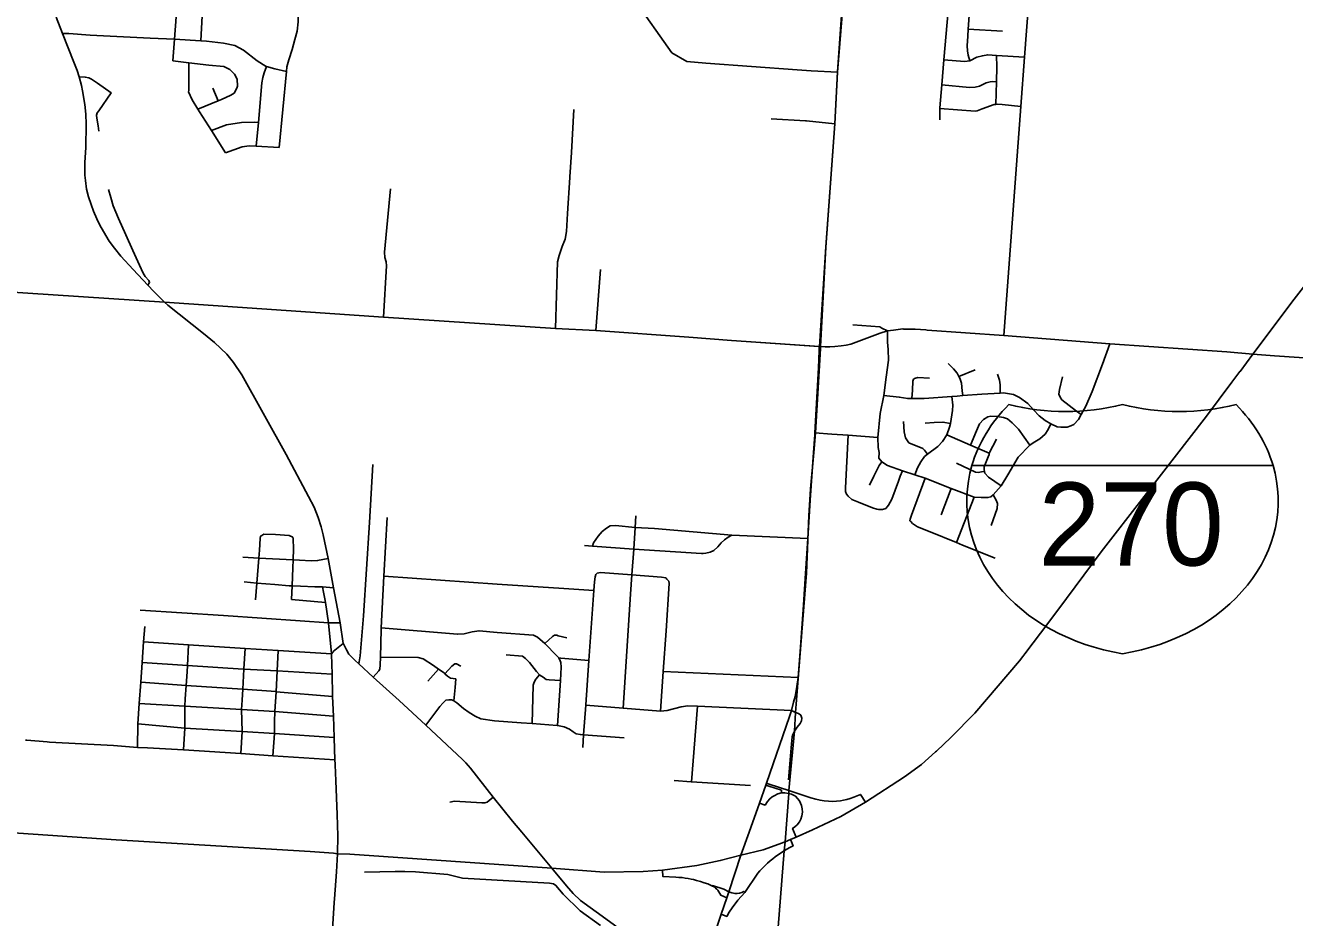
# Model space of a CAD drawing. Extents: x 1755200 to 1902939, y 644115 to 788070.
# Drawn here: x 1838211 to 1853497, y 681325 to 692073 of the extents above; entities that cross this region are included whole.
import ezdxf

# ---------------------------------------------------------------- set-up
doc = ezdxf.new("R2010")
doc.units = 0
for name, color, linetype in [('GM_X_City_Street', 7, 'Continuous'), ('GM_X_County_Road', 7, 'Continuous'), ('GM_X_Interchange_Ramps', 7, 'Continuous'), ('GM_X_Interstate_Route', 7, 'Continuous'), ('GM_X_Interstate_Shield', 7, 'Continuous'), ('GM_X_Township', 7, 'Continuous')]:
    doc.layers.add(name, color=color, linetype=linetype)

msp = doc.modelspace()

# ---------------------------------------------------------------- linework, layer by layer
at = {"layer": 'GM_X_City_Street'}
for points in [[(1840323, 691887), (1840356, 692494), (1840372, 692805), (1840373, 692814), (1840380, 692899), (1840402, 692971), (1840455, 693057), (1840481, 693100), (1840756, 693487), (1840776, 693552), (1840782, 693644), (1840793, 693749), (1840828, 694069)], [(1847676, 691527), (1847506, 691537), (1846406, 691618), (1846179, 691637), (1845998, 691744), (1845543, 692389), (1845432, 692563), (1845396, 692630), (1845365, 692816), (1845353, 692917), (1845358, 693015), (1845396, 693399), (1845412, 693692), (1845413, 693751)], [(1849993, 688339), (1850200, 691096), (1850245, 691692), (1850400, 693755)], [(1839985, 691645), (1840007, 691907), (1840026, 692176), (1840039, 692497), (1840044, 692575)], [(1849223, 690935), (1849225, 691071), (1849225, 691081), (1849248, 691356), (1849274, 691657), (1849314, 692113), (1849332, 692325)], [(1849585, 691648), (1849565, 691716), (1849559, 691766), (1849553, 691827), (1849560, 691943), (1849567, 692026), (1849587, 692305)], [(1838580, 692171), (1838658, 691975), (1838795, 691631), (1838833, 691530), (1838859, 691453), (1838885, 691349), (1838900, 691285), (1838928, 691120), (1838940, 691004), (1838945, 690884), (1838939, 690604), (1838929, 690423), (1838927, 690333), (1838929, 690271), (1838934, 690206), (1838949, 690101), (1838973, 690010), (1839002, 689916), (1839031, 689837), (1839071, 689745), (1839107, 689667), (1839152, 689589), (1839221, 689475), (1839283, 689389), (1839361, 689295), (1839511, 689131), (1839687, 688943), (1839759, 688869), (1839886, 688739)], [(1841491, 692249), (1841497, 692207), (1841495, 692116), (1841486, 692002), (1841458, 691904), (1841423, 691784), (1841383, 691659), (1841361, 691573), (1841354, 691516), (1841267, 690603)], [(1847992, 691508), (1848048, 692200)], [(1849567, 692026), (1849979, 692005)], [(1838658, 691975), (1838736, 691975), (1838991, 691954), (1839714, 691918), (1840007, 691907)], [(1840007, 691907), (1840323, 691887), (1840391, 691883), (1840598, 691859), (1840734, 691830), (1840838, 691776), (1841003, 691646), (1841109, 691580), (1841115, 691579), (1841215, 691549), (1841354, 691516)], [(1849274, 691657), (1849523, 691640), (1849585, 691648), (1849668, 691691), (1849736, 691707), (1849802, 691719), (1849906, 691711), (1850245, 691692)], [(1849900, 691122), (1849905, 691395), (1849909, 691573), (1849906, 691711)], [(1839985, 691645), (1840180, 691622), (1840421, 691595), (1840603, 691578), (1840674, 691543), (1840731, 691486), (1840761, 691427), (1840765, 691343), (1840757, 691319)], [(1840180, 691622), (1840178, 691287), (1840176, 691271), (1840220, 691175), (1840289, 691065), (1840310, 691031), (1840451, 690808), (1840622, 690537)], [(1840991, 690618), (1841017, 690902), (1841060, 691381), (1841071, 691447), (1841088, 691501), (1841115, 691579)], [(1847992, 691508), (1847676, 691527)], [(1839095, 690800), (1839088, 690862), (1839073, 690954), (1839068, 690993), (1839076, 691018), (1839094, 691044), (1839244, 691262), (1839080, 691376), (1839006, 691427), (1838976, 691443), (1838933, 691451), (1838859, 691453)], [(1847773, 688206), (1847853, 689404), (1847959, 690888), (1847992, 691508)], [(1849248, 691356), (1849581, 691327), (1849651, 691331), (1849703, 691342), (1849783, 691380), (1849831, 691394), (1849855, 691398), (1849905, 691395)], [(1840289, 691065), (1840533, 691163), (1840573, 691179), (1840686, 691232), (1840724, 691257), (1840757, 691319)], [(1840533, 691163), (1840469, 691317)], [(1844769, 690248), (1844787, 690541), (1844815, 691061)], [(1849225, 691071), (1849650, 691041), (1849672, 691043), (1849732, 691067), (1849878, 691120), (1849900, 691122), (1849914, 691124), (1849974, 691120), (1850200, 691096), (1850206, 691095)], [(1840451, 690808), (1840634, 690874), (1840815, 690903), (1840971, 690909), (1841017, 690902)], [(1847192, 690947), (1847607, 690924), (1847619, 690923)], [(1847619, 690923), (1847959, 690888)], [(1840622, 690537), (1840823, 690610), (1840907, 690623), (1840991, 690618), (1841267, 690603)], [(1844595, 688421), (1844621, 689227), (1844639, 689303), (1844675, 689410), (1844710, 689500), (1844726, 689592), (1844741, 689807), (1844768, 690240), (1844769, 690248)], [(1839687, 688943), (1839707, 688976), (1839698, 689000), (1839654, 689049), (1839630, 689087), (1839586, 689184), (1839505, 689360), (1839421, 689550), (1839333, 689748), (1839270, 689899), (1839241, 689999), (1839214, 690098)], [(1842524, 688560), (1842562, 689176), (1842558, 689226), (1842539, 689278), (1842537, 689343), (1842607, 690105)], [(1845081, 688396), (1845138, 689133)], [(1836126, 688986), (1837200, 688915), (1839886, 688739), (1842524, 688560), (1844595, 688421), (1845081, 688396), (1846201, 688317), (1846717, 688279), (1847773, 688206)], [(1839886, 688739), (1839927, 688705)], [(1839927, 688705), (1840355, 688360), (1840489, 688253), (1840637, 688114), (1840717, 688014), (1840817, 687862), (1841350, 686903), (1841620, 686399), (1841690, 686271), (1841738, 686144), (1841773, 686033), (1841797, 685935), (1841856, 685650), (1841922, 685300), (1842001, 684875), (1842039, 684627), (1842045, 684615)], [(1848175, 688467), (1848503, 688444), (1848525, 688426), (1848595, 688393)], [(1847773, 688206), (1847845, 688202), (1847900, 688202), (1847961, 688205), (1848034, 688212), (1848094, 688222), (1848151, 688233), (1848507, 688364), (1848593, 688392)], [(1848495, 686930), (1848481, 686990), (1848479, 687109), (1848505, 687397), (1848549, 687615), (1848579, 687836), (1848605, 688041), (1848602, 688171), (1848594, 688259), (1848595, 688393)], [(1848804, 688416), (1848895, 688414), (1848911, 688413)], [(1847771, 688152), (1847772, 688192), (1847773, 688206)], [(1850757, 687232), (1850803, 687248), (1850839, 687266), (1850893, 687326), (1850925, 687385), (1850981, 687485), (1851060, 687664), (1851182, 687991), (1851271, 688239)], [(1847717, 687141), (1847719, 687167), (1847762, 687948), (1847771, 688152)], [(1853256, 688094), (1854025, 688040), (1855415, 687939), (1856313, 687875), (1856498, 687863), (1856659, 687849)], [(1849500, 687613), (1849494, 687671), (1849484, 687763), (1849464, 687825), (1849453, 687845), (1849431, 687883), (1849389, 687937), (1849323, 688001)], [(1849453, 687845), (1849648, 687924)], [(1849952, 687644), (1849951, 687742), (1849941, 687801), (1849919, 687871)], [(1848885, 687579), (1848893, 687679), (1848900, 687789), (1848908, 687811), (1848920, 687819), (1848960, 687833), (1849101, 687822)], [(1850925, 687385), (1850871, 687425), (1850694, 687564), (1850674, 687596), (1850659, 687630), (1850667, 687687), (1850701, 687841)], [(1848549, 687615), (1848736, 687596), (1848837, 687578), (1848885, 687579), (1849035, 687579), (1849370, 687604), (1849434, 687608), (1849500, 687613), (1849731, 687631), (1849952, 687644), (1849992, 687646), (1850110, 687627), (1850184, 687591), (1850285, 687517), (1850353, 687443), (1850422, 687371), (1850492, 687315), (1850562, 687273), (1850639, 687239), (1850682, 687235), (1850757, 687232)], [(1848921, 686661), (1848954, 686742), (1848994, 686817), (1849038, 686879), (1849077, 686909), (1849200, 687002), (1849258, 687060), (1849309, 687140), (1849341, 687235), (1849352, 687277), (1849377, 687436), (1849379, 687500), (1849370, 687604)], [(1848786, 687303), (1848796, 687179), (1848812, 687107), (1848851, 687045), (1848917, 687015), (1848991, 686989), (1849021, 686977), (1849040, 686955), (1849077, 686909)], [(1849046, 687282), (1849157, 687289), (1849261, 687295), (1849352, 687277)], [(1849593, 687018), (1849664, 687190), (1849702, 687274), (1849748, 687327), (1849802, 687357), (1849840, 687365), (1849916, 687363), (1849991, 687349), (1850039, 687332), (1850095, 687284), (1850172, 687210), (1850308, 687016)], [(1849785, 686388), (1849803, 686386), (1849838, 686394), (1849868, 686417), (1849964, 686525), (1850043, 686660), (1850167, 686871), (1850308, 687016), (1850349, 687044), (1850427, 687094), (1850493, 687150), (1850529, 687205), (1850562, 687273)], [(1847414, 683750), (1847438, 683821), (1847463, 683922), (1847481, 683991), (1847493, 684058), (1847506, 684137), (1847517, 684220), (1847545, 684584), (1847583, 685092), (1847605, 685472), (1847634, 685893), (1847662, 686354), (1847702, 686929), (1847717, 687141)], [(1847719, 687167), (1847924, 687150), (1848120, 687136), (1848479, 687109)], [(1848120, 687136), (1848089, 686503), (1848089, 686459), (1848101, 686425), (1848119, 686401), (1848163, 686361), (1848244, 686329), (1848412, 686263), (1848466, 686247), (1848486, 686243)], [(1849309, 687140), (1849593, 687018), (1849792, 686934), (1849820, 686920), (1849818, 686904), (1849806, 686875), (1849758, 686757), (1849756, 686721), (1849761, 686699), (1849766, 686679), (1849811, 686633), (1849964, 686525)], [(1849820, 686920), (1849905, 687088)], [(1842225, 684382), (1842243, 684478), (1842285, 684961), (1842356, 686084), (1842395, 686784)], [(1848375, 686534), (1848429, 686644), (1848495, 686773), (1848527, 686815)], [(1848495, 686930), (1848488, 686861), (1848527, 686815), (1848593, 686773), (1848774, 686709), (1848921, 686661), (1849048, 686621), (1849361, 686494), (1849636, 686390), (1849721, 686386), (1849785, 686388)], [(1849423, 686800), (1849654, 686690), (1849684, 686687), (1849724, 686695), (1849761, 686699)], [(1848486, 686243), (1848535, 686242), (1848573, 686254), (1848607, 686292), (1848644, 686366), (1848726, 686585), (1848746, 686643), (1848774, 686709)], [(1848876, 686096), (1848864, 686106), (1848868, 686126), (1848882, 686173), (1849048, 686621)], [(1849241, 686176), (1849361, 686494)], [(1849423, 685844), (1849636, 686390)], [(1849843, 686047), (1849914, 686252), (1849920, 686312), (1849902, 686356), (1849868, 686417)], [(1842400, 684224), (1842467, 684297), (1842478, 684320), (1842483, 684371), (1842486, 684464), (1842496, 684796), (1842497, 684816), (1842530, 685437), (1842568, 686145)], [(1845041, 685802), (1845052, 685842), (1845110, 685921), (1845156, 685975), (1845208, 686015), (1845254, 686046), (1845320, 686048), (1845554, 686025), (1845789, 686011), (1846721, 685934)], [(1845410, 683847), (1845499, 685220), (1845515, 685454), (1845537, 685765), (1845554, 686025), (1845564, 686167)], [(1848876, 686096), (1848896, 686072), (1848954, 686034), (1849109, 685971), (1849423, 685844), (1849498, 685813), (1849499, 685813)], [(1840983, 685153), (1840999, 685356), (1841023, 685657), (1841031, 685751), (1841038, 685891), (1841044, 685919), (1841060, 685927)], [(1841060, 685927), (1841082, 685946), (1841224, 685940), (1841389, 685929), (1841431, 685909)], [(1841417, 685159), (1841424, 685322), (1841432, 685540), (1841435, 685635), (1841439, 685768), (1841437, 685889), (1841431, 685909)], [(1845041, 685802), (1845537, 685765), (1846355, 685712), (1846373, 685712), (1846407, 685717), (1846457, 685729), (1846501, 685749), (1846549, 685793), (1846589, 685839), (1846631, 685876), (1846673, 685908), (1846721, 685934)], [(1846721, 685934), (1847634, 685893)], [(1844946, 685808), (1845041, 685802)], [(1849499, 685813), (1849892, 685654)], [(1840831, 685668), (1841023, 685657), (1841435, 685635), (1841514, 685630), (1841652, 685623), (1841730, 685627), (1841856, 685650)], [(1842530, 685437), (1843892, 685342), (1844697, 685290)], [(1844960, 683890), (1844998, 684423), (1845059, 685267), (1845066, 685371), (1845072, 685432), (1845080, 685460), (1845098, 685474)], [(1845098, 685474), (1845136, 685482), (1845515, 685454), (1845873, 685428), (1845923, 685420), (1845937, 685402), (1845941, 685398)], [(1840846, 685369), (1840999, 685356), (1841214, 685337), (1841387, 685323), (1841424, 685322), (1841525, 685318), (1841699, 685312), (1841788, 685309), (1841922, 685300)], [(1841897, 684513), (1841863, 684870), (1841862, 684876), (1841824, 685122), (1841820, 685146), (1841802, 685246), (1841788, 685309)], [(1844697, 685290), (1844697, 685290), (1845059, 685267)], [(1845859, 683813), (1845893, 684290), (1845927, 684781), (1845964, 685352), (1845959, 685380), (1845941, 685398)], [(1841417, 685159), (1841824, 685122)], [(1839593, 685030), (1840599, 684964), (1841522, 684901), (1841862, 684876), (1841894, 684876)], [(1839562, 683375), (1839565, 683661), (1839582, 683906), (1839600, 684162), (1839617, 684399), (1839635, 684648), (1839648, 684832)], [(1841894, 684876), (1842001, 684875)], [(1842497, 684816), (1843416, 684741), (1843418, 684741)], [(1839635, 684648), (1840177, 684611), (1840859, 684568), (1841255, 684544), (1841898, 684505), (1841917, 684529)], [(1843418, 684741), (1843494, 684743), (1843592, 684767), (1843676, 684782), (1843894, 684762), (1844329, 684726), (1844377, 684704), (1844467, 684626), (1844610, 684478), (1844637, 684456), (1844661, 684452), (1844998, 684423)], [(1844467, 684626), (1844558, 684710), (1844584, 684728), (1844610, 684726), (1844628, 684720), (1844730, 684695)], [(1840117, 683345), (1840133, 683607), (1840131, 683874), (1840137, 683962), (1840148, 684122), (1840158, 684285), (1840163, 684361), (1840177, 684611)], [(1840805, 683302), (1840822, 683567), (1840814, 683834), (1840820, 683946), (1840828, 684078), (1840843, 684319), (1840843, 684321), (1840859, 684568)], [(1841193, 683273), (1841210, 683544), (1841210, 683689), (1841217, 683807), (1841231, 684047), (1841243, 684298), (1841255, 684544)], [(1841936, 683226), (1841930, 683491), (1841929, 683495), (1841920, 683754), (1841911, 683988), (1841910, 684008), (1841904, 684260), (1841898, 684499), (1841898, 684505), (1841897, 684513)], [(1841917, 684529), (1841918, 684530), (1842039, 684627)], [(1842045, 684615), (1842077, 684551), (1842108, 684501), (1842142, 684461), (1842157, 684445), (1842183, 684423), (1842225, 684382), (1842400, 684224), (1842714, 683939), (1843032, 683645), (1843474, 683231), (1843517, 683189), (1843573, 683125), (1843844, 682777), (1844078, 682489)], [(1844003, 684490), (1844198, 684475), (1844234, 684447), (1844284, 684397), (1844367, 684289), (1844402, 684250), (1844405, 684247), (1844445, 684221), (1844485, 684195), (1844519, 684191), (1844655, 684183)], [(1839617, 684399), (1840163, 684361), (1840835, 684319), (1840843, 684319), (1841243, 684298), (1841904, 684260)], [(1842486, 684464), (1842942, 684458), (1843002, 684441), (1843128, 684361), (1843188, 684318), (1843219, 684297), (1843257, 684271), (1843264, 684264), (1843294, 684236)], [(1843264, 684264), (1843345, 684353), (1843383, 684384), (1843403, 684382), (1843455, 684354)], [(1844621, 683639), (1844655, 684183), (1844665, 684344), (1844661, 684398), (1844653, 684418), (1844637, 684456)], [(1843059, 684174), (1843188, 684318)], [(1843294, 684236), (1843295, 684235), (1843329, 684211), (1843395, 684201)], [(1843371, 683935), (1843386, 684099), (1843395, 684201)], [(1844315, 683663), (1844327, 684124), (1844337, 684162), (1844357, 684196), (1844402, 684250)], [(1845893, 684290), (1847517, 684220)], [(1839600, 684162), (1840148, 684122), (1840824, 684078), (1840828, 684078), (1841227, 684048), (1841231, 684047), (1841911, 683988)], [(1839582, 683906), (1840131, 683874), (1840814, 683834), (1841217, 683807), (1841920, 683754)], [(1843032, 683645), (1843204, 683869), (1843240, 683910), (1843274, 683944), (1843310, 683950), (1843341, 683947), (1843353, 683945)], [(1843353, 683945), (1843356, 683945), (1843371, 683935), (1843408, 683911), (1843489, 683845), (1843557, 683795), (1843627, 683753), (1843696, 683719), (1843860, 683696), (1844182, 683673), (1844315, 683663), (1844615, 683640), (1844621, 683639), (1844699, 683622), (1844766, 683594), (1844810, 683564), (1844844, 683541), (1844896, 683531), (1844934, 683528), (1845421, 683490)], [(1844923, 683376), (1844934, 683528), (1844959, 683886), (1844960, 683890)], [(1844959, 683886), (1845410, 683847), (1845859, 683813), (1845939, 683819), (1846107, 683865), (1846189, 683876), (1846305, 683871), (1847438, 683821)], [(1846234, 682963), (1846305, 683871)], [(1847129, 682920), (1847138, 682944), (1847414, 683750)], [(1847438, 683821), (1847484, 683798), (1847522, 683785), (1847550, 683764), (1847564, 683729), (1847560, 683695), (1847543, 683663), (1847506, 683620), (1847472, 683572), (1847464, 683557)], [(1839565, 683661), (1840133, 683607), (1840822, 683567), (1841210, 683544), (1841929, 683495)], [(1838211, 683463), (1838229, 683462), (1838473, 683443)], [(1847464, 683557), (1847453, 683533), (1847445, 683502), (1847432, 683370), (1847402, 682986)], [(1839418, 683386), (1839562, 683375), (1839680, 683369)], [(1839680, 683369), (1840117, 683345), (1840805, 683302), (1841193, 683273), (1841936, 683226)], [(1841942, 683174), (1841936, 683226)], [(1846024, 682977), (1846228, 682963)], [(1846228, 682963), (1846228, 682963), (1846234, 682963), (1846944, 682916)], [(1846829, 682076), (1846928, 682353), (1847051, 682706), (1847129, 682920)], [(1843322, 682716), (1843378, 682728), (1843709, 682709), (1843743, 682708), (1843772, 682718), (1843844, 682777)], [(1844078, 682489), (1844188, 682354), (1844551, 681922), (1844726, 681707), (1844810, 681617), (1844897, 681531), (1845201, 681310), (1845410, 681158), (1845583, 681058), (1845591, 681054)], [(1846347, 680664), (1846355, 680687), (1846517, 681151), (1846591, 681367), (1846659, 681565), (1846683, 681635), (1846829, 682076)], [(1842294, 681874), (1842664, 681882), (1842782, 681880), (1842910, 681878), (1843299, 681844), (1843475, 681802), (1844522, 681742), (1844571, 681732)], [(1845136, 681229), (1844893, 681409), (1844689, 681610), (1844600, 681713), (1844571, 681732)]]:
    msp.add_lwpolyline(points, dxfattribs=at)
at = {"layer": 'GM_X_County_Road'}
for points in [[(1848593, 688392), (1848595, 688393), (1848668, 688402), (1848779, 688417), (1848789, 688416), (1848804, 688416)], [(1848911, 688413), (1848927, 688413), (1849055, 688404), (1849070, 688403)], [(1849070, 688403), (1849993, 688339), (1851271, 688239), (1852679, 688139), (1852994, 688113), (1853256, 688094), (1853256, 688094)], [(1838473, 683443), (1838500, 683441), (1839271, 683398), (1839418, 683386)], [(1841933, 681550), (1841959, 681877), (1841972, 682095), (1841975, 682311), (1841966, 682568), (1841949, 682972), (1841943, 683166), (1841942, 683174)], [(1841753, 678933), (1841756, 678966), (1841791, 679364), (1841862, 680408), (1841930, 681509), (1841933, 681550)]]:
    msp.add_lwpolyline(points, dxfattribs=at)
at = {"layer": 'GM_X_Interchange_Ramps'}
for points in [[(1847051, 682706), (1847119, 682682), (1847149, 682723), (1847176, 682757), (1847203, 682779), (1847227, 682794), (1847273, 682817), (1847318, 682827), (1847355, 682830), (1847404, 682821), (1847437, 682812), (1847484, 682787), (1847511, 682760), (1847533, 682732), (1847547, 682705), (1847559, 682675), (1847568, 682636), (1847570, 682596), (1847564, 682551), (1847551, 682511), (1847534, 682479), (1847505, 682445), (1847479, 682421), (1847451, 682400), (1847492, 682293)], [(1847129, 682920), (1847163, 682909), (1847316, 682859), (1847318, 682827)], [(1848329, 682717), (1848268, 682810), (1848229, 682792), (1848189, 682776), (1848146, 682761), (1848106, 682749), (1848063, 682740), (1848027, 682734), (1847981, 682729), (1847932, 682726), (1847883, 682727), (1847830, 682732), (1847781, 682740), (1847732, 682751), (1847672, 682770), (1847404, 682857), (1847170, 682932), (1847138, 682944)], [(1846591, 681367), (1846658, 681341), (1846687, 681391), (1846724, 681445), (1846793, 681535), (1846875, 681629), (1847034, 681863), (1847057, 681889), (1847088, 681921), (1847119, 681952), (1847148, 681980), (1847182, 682009), (1847213, 682035), (1847242, 682057), (1847281, 682085), (1847350, 682131), (1847380, 682149), (1847417, 682169), (1847457, 682189), (1847427, 682266)], [(1845884, 681896), (1845890, 681820), (1846044, 681812), (1846081, 681810), (1846121, 681807), (1846159, 681802), (1846192, 681797), (1846229, 681790), (1846259, 681783), (1846295, 681774), (1846343, 681760), (1846387, 681746), (1846429, 681731), (1846485, 681704), (1846505, 681695), (1846524, 681682), (1846538, 681668), (1846550, 681656), (1846563, 681638), (1846574, 681617), (1846585, 681595), (1846659, 681565)], [(1846485, 681704), (1846487, 681711), (1846624, 681667), (1846683, 681635)], [(1846683, 681635), (1846720, 681625), (1846758, 681616), (1846784, 681615), (1846811, 681619), (1846838, 681628), (1846864, 681642), (1846875, 681629)]]:
    msp.add_lwpolyline(points, dxfattribs=at)
at = {"layer": 'GM_X_Interstate_Route'}
for points in [[(1855721, 691691), (1855482, 691365), (1854785, 690465), (1854227, 689720), (1853491, 688775), (1852994, 688113)], [(1852994, 688113), (1852840, 687906), (1852838, 687905)], [(1852838, 687905), (1852741, 687774), (1852437, 687366), (1851683, 686397), (1851166, 685731), (1850647, 685030), (1850558, 684912), (1850538, 684886)], [(1850538, 684886), (1850248, 684503), (1850224, 684472)], [(1850224, 684472), (1850183, 684418), (1849646, 683789), (1849356, 683495), (1849183, 683330), (1849173, 683321)], [(1849173, 683321), (1849003, 683172), (1848798, 683022), (1848329, 682717), (1848032, 682542), (1847692, 682384), (1847492, 682293), (1847427, 682266), (1847361, 682239), (1847337, 682230)], [(1841920, 682100), (1841640, 682123), (1839305, 682261), (1836772, 682434), (1835570, 682508), (1833954, 682610), (1832722, 682699), (1831362, 682779), (1830900, 682805), (1829749, 682893), (1829502, 682912), (1828812, 682963), (1828423, 683029), (1828275, 683054), (1827751, 683161)], [(1847337, 682230), (1847330, 682226), (1847095, 682143), (1846829, 682076)], [(1846829, 682076), (1846579, 682012), (1846297, 681953), (1845884, 681896), (1845650, 681882), (1845182, 681874), (1844551, 681922), (1842117, 682088), (1841972, 682095), (1841920, 682100)]]:
    msp.add_lwpolyline(points, dxfattribs=at)
at = {"layer": 'GM_X_Interstate_Shield'}
msp.add_line((1853236, 686770), (1849610, 686770), dxfattribs=at)
msp.add_line((1853236, 686770), (1849610, 686770), dxfattribs=at)
for centre, start_param, end_param in [((1851892, 686342), 2.47259, 2.911027), ((1850739, 689298), 4.415841, 5.008937), ((1852108, 689298), 4.415841, 5.008937), ((1850955, 686342), 0.230566, 0.669003), ((1851892, 686342), 2.911027, 4.511031), ((1850955, 686342), 4.913747, 6.513751)]:
    msp.add_ellipse(centre, major_axis=(2344, 0), ratio=0.8, start_param=start_param, end_param=end_param, dxfattribs=at)
at = {"layer": 'GM_X_Township'}
for points in [[(1846672, 671849), (1846785, 673538), (1846869, 674912), (1846962, 676601), (1847206, 680290), (1847350, 682131), (1847361, 682239), (1847404, 682821), (1847404, 682857), (1847472, 683572), (1847484, 683798), (1847618, 685474), (1847648, 686168), (1847667, 686490), (1847707, 686929), (1847728, 687165), (1847787, 688183), (1847788, 688204), (1847850, 689401), (1847959, 690888), (1847991, 691512), (1848200, 694479)], [(1847787, 688183), (1847788, 688204), (1847765, 688206), (1846717, 688279), (1846201, 688317), (1845081, 688396), (1844595, 688421), (1842524, 688560), (1839886, 688739), (1837200, 688915), (1836126, 688986), (1835345, 689037), (1835300, 689039), (1834004, 689124), (1833303, 689177), (1832253, 689251), (1831848, 689276), (1831201, 689315), (1830621, 689354), (1830238, 689382), (1829166, 689438), (1826839, 689523)]]:
    msp.add_lwpolyline(points, dxfattribs=at)

# ---------------------------------------------------------------- texts
at = {"layer": 'GM_X_Interstate_Shield'}
msp.add_text('270', height=1000, dxfattribs=at).set_placement((1850413, 685567))

doc.saveas('drawing.dxf')
